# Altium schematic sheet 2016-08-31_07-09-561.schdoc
size 285 x 121 mm; SheetNumber: 1; SheetTotal: 1
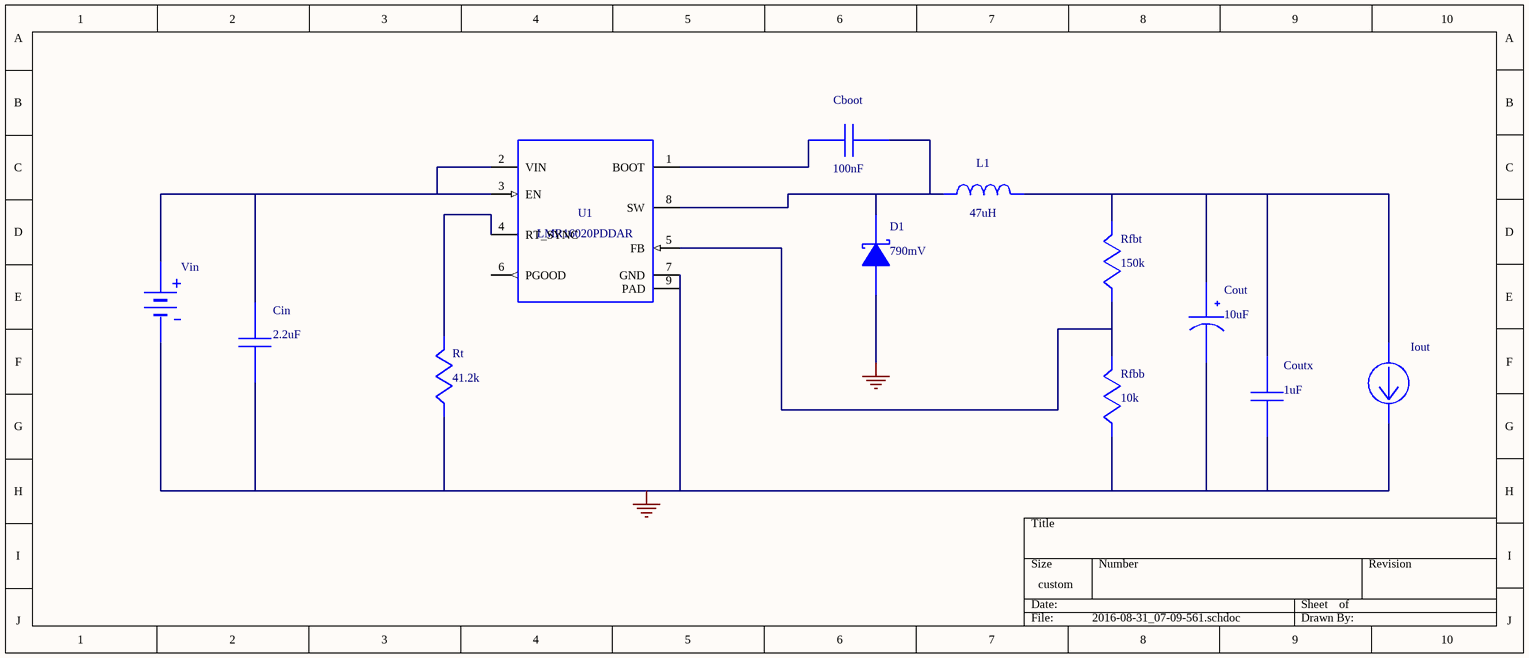
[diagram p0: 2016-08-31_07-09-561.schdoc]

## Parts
Cboot  value 100nF  (hidden comment: HMK212B7104KG-T)
Cin  value 2.2uF  (hidden comment: C3225X7R2A225K230AB)
Cout  value 10uF  (hidden comment: 593D106X9035D2TE3)
Coutx  value 1uF  (hidden comment: GRM188R61E105KA12D)
D1  value 790mV  (hidden comment: B1100-13-F)
Iout  WB_CURRENT_LOAD  (value not drawn)
L1  value 47uH  (hidden comment: SRU1048-470Y)
Rfbb  value 10k  (hidden comment: CRCW040210K0FKED)
Rfbt  value 150k  (hidden comment: CRCW0402150KFKED)
Rt  value 41.2k  (hidden comment: CRCW040241K2FKED)
U1  LMR16020PDDAR
Vin  WB_BATTERY  (value not drawn)

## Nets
0: Cin.2 Cout.2(-) Coutx.2 D1.2(A) Iout.2(-) Rfbb.2 Rt.2 U1.7(GND) U1.9(PAD) Vin.2(-)
NetCboot_1: Cboot.1 U1.1(BOOT)
NetCboot_2: Cboot.2 D1.1(K) L1.1 U1.8(SW)
NetCin_1: Cin.1 U1.2(VIN) U1.3(EN) Vin.1(+)
NetCout_1: Cout.1(+) Coutx.1 Iout.1(+) L1.2 Rfbt.1
NetRfbb_1: Rfbb.1 Rfbt.2 U1.5(FB)
NetRt_1: Rt.1 U1.4(RT_SYNC)

Not connected (* = marked no-connect by the designer): U1 6(PGOOD)

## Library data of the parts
Cboot = HMK212B7104KG-T: Manufacturer Name: Taiyo Yuden
Cin = C3225X7R2A225K230AB: C3225X7R2A225K23; Manufacturer Name: TDK
Cout = 593D106X9035D2TE3: 593D106X9035D2TE; Manufacturer Name: Vishay-Sprague
Coutx = GRM188R61E105KA12D: GRM188R61E105KA1; Manufacturer Name: MuRata
D1 = B1100-13-F: Manufacturer Name: Diodes Inc.
L1 = SRU1048-470Y: Manufacturer Name: Bourns
Rfbb = CRCW040210K0FKED: Manufacturer Name: Vishay-Dale
Rfbt = CRCW0402150KFKED: Manufacturer Name: Vishay-Dale
Rt = CRCW040241K2FKED: Manufacturer Name: Vishay-Dale
U1 = LMR16020PDDAR: Manufacturer Name: Texas Instruments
